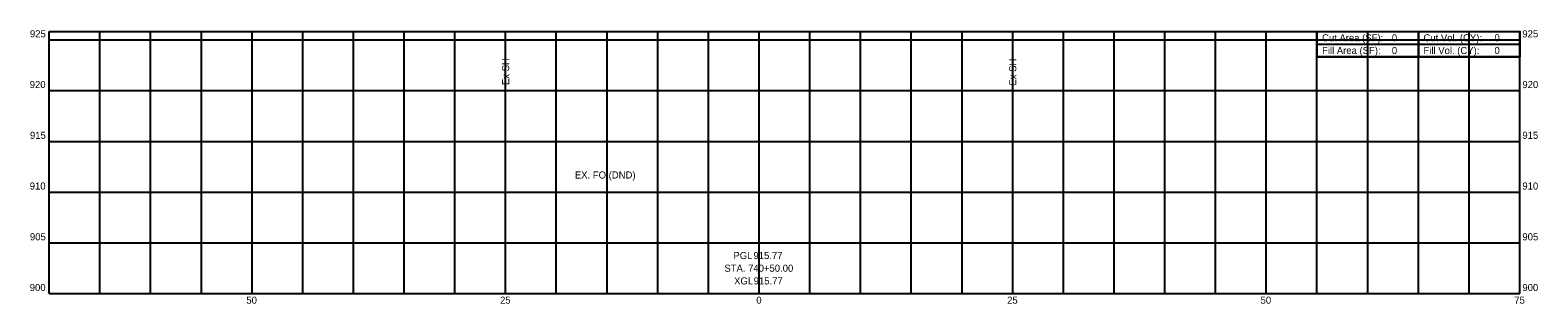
# Model space of a CAD drawing. Extents: x -72 to 77, y 899 to 926.
import ezdxf

# ---------------------------------------------------------------- set-up
doc = ezdxf.new("R2010")
doc.units = 0
for name, color, linetype in [('Default', 7, 'Continuous'), ('RW_X_Esmt_SH', 7, 'Continuous'), ('SH_Data', 7, 'Continuous'), ('SH_Major_Grid_Line', 7, 'Continuous'), ('SH_Masking', 7, 'Continuous'), ('SH_Text', 7, 'Continuous')]:
    doc.layers.add(name, color=color, linetype=linetype)

msp = doc.modelspace()

# ---------------------------------------------------------------- linework, layer by layer
at = {"layer": 'Default'}
msp.add_circle((75, 925.84), 0.000417, dxfattribs=at)
msp.add_circle((75, 925.84), 0.000417, dxfattribs=at)
msp.add_circle((75, 925.84), 0.000417, dxfattribs=at)
msp.add_circle((75, 925.84), 0.000417, dxfattribs=at)
msp.add_circle((75, 925.84), 0.000417, dxfattribs=at)
msp.add_circle((75, 925.84), 0.000417, dxfattribs=at)
msp.add_circle((75, 925.84), 0.000417, dxfattribs=at)
msp.add_circle((75, 925.84), 0.000417, dxfattribs=at)
msp.add_circle((75, 925.84), 0.000417, dxfattribs=at)
msp.add_circle((75, 925.84), 0.000417, dxfattribs=at)
msp.add_circle((75, 925.84), 0.000417, dxfattribs=at)
msp.add_circle((75, 925.84), 0.000417, dxfattribs=at)
at = {"layer": 'RW_X_Esmt_SH'}
for p, q in [((-25, 915.05), (-25, 920.05)), ((25, 915), (25, 920))]:
    msp.add_line(p, q, dxfattribs=at)
at = {"layer": 'SH_Data'}
for p, q in [((55, 925.84), (75, 925.84)), ((55, 925.84), (55, 923.34)), ((65, 925.84), (65, 923.34)), ((75, 925.84), (75, 923.34)), ((55, 924.59), (75, 924.59)), ((55, 923.34), (75, 923.34))]:
    msp.add_line(p, q, dxfattribs=at)
at = {"layer": 'SH_Major_Grid_Line'}
for p, q in [((-70, 925.84), (75, 925.84)), ((-70, 900), (-70, 925.84)), ((-70, 925), (75, 925)), ((-65, 900), (-65, 925.84)), ((-60, 900), (-60, 925.84)), ((-55, 900), (-55, 925.84)), ((-50, 900), (-50, 925.84)), ((-45, 900), (-45, 925.84)), ((-40, 900), (-40, 925.84)), ((-35, 900), (-35, 925.84)), ((-30, 900), (-30, 925.84)), ((-25, 900), (-25, 925.84)), ((-20, 900), (-20, 925.84)), ((-15, 900), (-15, 925.84)), ((-10, 900), (-10, 925.84)), ((-5, 900), (-5, 925.84)), ((0, 900), (0, 925.84)), ((5, 900), (5, 925.84)), ((10, 900), (10, 925.84)), ((15, 900), (15, 925.84)), ((20, 900), (20, 925.84)), ((25, 900), (25, 925.84)), ((30, 900), (30, 925.84)), ((35, 900), (35, 925.84)), ((40, 900), (40, 925.84)), ((45, 900), (45, 925.84)), ((50, 900), (50, 925.84)), ((55, 900), (55, 925.84)), ((60, 900), (60, 925.84)), ((65, 900), (65, 925.84)), ((70, 900), (70, 925.84)), ((75, 900), (75, 925.84)), ((-70, 920), (75, 920)), ((-70, 915), (75, 915)), ((-70, 910), (75, 910)), ((-70, 905), (75, 905)), ((-70, 900), (75, 900))]:
    msp.add_line(p, q, dxfattribs=at)
at = {"layer": 'SH_Masking'}
msp.add_lwpolyline([(55, 925.84), (75, 925.84), (75, 923.34), (55, 923.34)], close=True, dxfattribs=at)

# ---------------------------------------------------------------- texts
at = {"layer": 'RW_X_Esmt_SH'}
for p in [(-24.65, 920.55), (25.35, 920.5)]:
    msp.add_text('Ex SH', height=0.7, rotation=90, dxfattribs=at).set_placement(p)
at = {"layer": 'SH_Text'}
for s, p in [('925', (-71.9, 925.25)), ('Cut Area (SF):', (55.5, 924.86)), ('0', (62.38, 924.86)), ('Cut Vol. (CY):', (65.5, 924.86)), ('0', (72.5, 924.86)), ('925', (75.25, 925.25)), ('Fill Area (SF):', (55.5, 923.61)), ('0', (62.38, 923.61)), ('Fill Vol. (CY):', (65.5, 923.61)), ('0', (72.5, 923.61)), ('920', (-71.92, 920.25)), ('920', (75.25, 920.25)), ('915', (-71.9, 915.25)), ('915', (75.25, 915.25)), ('EX. FO (DND)', (-18.17, 911.34)), ('910', (-71.92, 910.25)), ('910', (75.25, 910.25)), ('905', (-71.9, 905.25)), ('905', (75.25, 905.25)), ('PGL ', (-2.54, 903.4)), ('915.77', (-0.56, 903.4)), ('STA. 740+50.00', (-3.43, 902.15)), ('900', (-71.92, 900.25)), ('XGL ', (-2.47, 900.9)), ('915.77', (-0.54, 900.9)), ('900', (75.25, 900.25)), ('50', (-50.56, 899)), ('25', (-25.55, 899)), ('0', (-0.28, 899)), ('25', (24.45, 899)), ('50', (49.44, 899)), ('75', (74.45, 899))]:
    msp.add_text(s, height=0.7, dxfattribs=at).set_placement(p)

doc.saveas('drawing.dxf')
